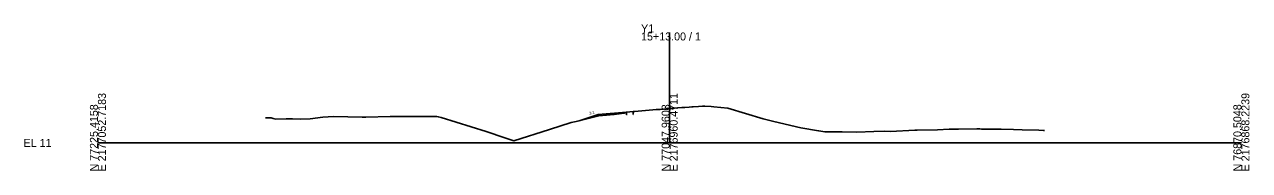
# Model space of a CAD drawing. Extents: x 2207892 to 2209721, y 61220 to 65449.
# Drawn here: x 2209292.5 to 2209721, y 61397.6 to 61448.8 of the extents above; entities that cross this region are included whole.
import ezdxf

# ---------------------------------------------------------------- set-up
doc = ezdxf.new("R2010")
doc.units = 0
for name, color, linetype in [('Exist DTM Breakline Cogo Point CELL', 7, 'Continuous'), ('Exist DTM Ridgeline Cogo Comment', 7, 'Continuous'), ('Exist Hydro Stream or Body of Water Cogo Elevation', 7, 'Continuous'), ('Exist Hydro Stream or Body of Water Cogo Point CELL', 7, 'Continuous'), ('Exist Roads EOP Other Cogo Elevation', 7, 'Continuous'), ('Exist Roads EOP Other Cogo Number', 7, 'Continuous')]:
    doc.layers.add(name, color=color, linetype=linetype)

msp = doc.modelspace()

# ---------------------------------------------------------------- linework, layer by layer
at = {"layer": 'Exist DTM Breakline Cogo Point CELL'}
for p, q in [((2209503.13, 61417.16), (2209503.13, 61418.1)), ((2209505.38, 61417.25), (2209505.38, 61418.31))]:
    msp.add_line(p, q, dxfattribs=at)
at = {"layer": 'Exist Hydro Stream or Body of Water Cogo Elevation'}
msp.add_lwpolyline([(2209493.13, 61417.3), (2209486.49, 61415.09)], dxfattribs=at)
at = {"layer": 'Exist Hydro Stream or Body of Water Cogo Point CELL'}
msp.add_lwpolyline([(2209503.13, 61418.1), (2209493.13, 61417.3)], dxfattribs=at)
at = {"layer": 'Exist Roads EOP Other Cogo Elevation'}
msp.add_lwpolyline([(2209376.82, 61416.13), (2209378.74, 61416.08), (2209379.48, 61415.91), (2209380.41, 61415.62), (2209383.97, 61415.7), (2209386.22, 61415.71), (2209388.9, 61415.61), (2209392.42, 61415.75), (2209396.89, 61416.32), (2209400.57, 61416.57), (2209410.64, 61416.31), (2209411.19, 61416.31), (2209411.92, 61416.32), (2209420.37, 61416.5), (2209434.63, 61416.56), (2209435.69, 61416.54), (2209436.71, 61416.5), (2209437.23, 61416.46), (2209438.23, 61416.18), (2209454.03, 61411.26), (2209460.51, 61409.07), (2209463.66, 61407.98), (2209476.15, 61411.98), (2209483.73, 61414.41), (2209485.46, 61414.83), (2209493.44, 61416.81), (2209498.79, 61417.24), (2209502.26, 61417.73), (2209503.12, 61418.1), (2209505.38, 61418.31), (2209505.97, 61418.34), (2209507.21, 61418.44), (2209508.47, 61418.55), (2209509.76, 61418.66), (2209510.97, 61418.75), (2209512.3, 61418.86), (2209513.47, 61418.95), (2209514.84, 61419.06), (2209515.97, 61419.15), (2209516.98, 61419.23), (2209517.33, 61419.26), (2209517.69, 61419.29), (2209518.47, 61419.36), (2209519.91, 61419.47), (2209520.97, 61419.55), (2209522.45, 61419.66), (2209523.47, 61419.74), (2209524.99, 61419.85), (2209525.97, 61419.92), (2209526.4, 61419.94), (2209528.23, 61420.06), (2209529.71, 61420.16), (2209530.11, 61420.19), (2209530.5, 61420.21), (2209532.64, 61420.04), (2209533.57, 61419.96), (2209538.5, 61419.5), (2209544.7, 61417.6), (2209550.88, 61415.74), (2209554.6, 61414.85), (2209564.02, 61412.6), (2209570.28, 61411.59), (2209572.52, 61411.18), (2209577.5, 61411.16), (2209578.52, 61411.19), (2209583.64, 61411.03), (2209589.6, 61411.26), (2209593.44, 61411.38), (2209595.39, 61411.24), (2209603.91, 61411.74), (2209604.71, 61411.76), (2209611.85, 61411.94), (2209615.97, 61412.11), (2209619.26, 61412.15), (2209625.59, 61412.19), (2209626.68, 61412.18), (2209627.24, 61412.17), (2209634.09, 61412.1), (2209638.51, 61412), (2209641.51, 61411.89), (2209647.27, 61411.72), (2209648.92, 61411.66), (2209649.26, 61411.65)], dxfattribs=at)
at = {"layer": 'Exist Roads EOP Other Cogo Number'}
for p, q in [((2209518.17, 61407.31), (2209518.17, 61446.01)), ((2209318.17, 61407.31), (2209518.17, 61407.31)), ((2209518.17, 61407.31), (2209718.17, 61407.31))]:
    msp.add_line(p, q, dxfattribs=at)

# ---------------------------------------------------------------- texts
at = {"layer": 'Exist DTM Breakline Cogo Point CELL'}
for s, height, p in [('23.02', 1, (2209516.26, 61418.83)), ('EOS', 0.1, (2209503.06, 61416.93)), ('EOP', 0.1, (2209505.29, 61416.93))]:
    msp.add_text(s, height=height, dxfattribs=at).set_placement(p)
at = {"layer": 'Exist DTM Ridgeline Cogo Comment'}
msp.add_text('3:1', height=1, rotation=18.4332, dxfattribs=at).set_placement((2209490.18, 61417.11))
at = {"layer": 'Exist Roads EOP Other Cogo Number'}
for s, p in [('Y1', (2209508.17, 61446.01)), ('15+13.00 / 1', (2209508.17, 61443.21)), ('EL 11', (2209292.17, 61405.91))]:
    msp.add_text(s, height=2.8, dxfattribs=at).set_placement(p)
for s, p in [('E 2177052.7183', (2209320.97, 61397.31)), ('E 2176960.4711', (2209520.97, 61397.31)), ('E 2176868.2239', (2209720.97, 61397.31)), ('N 77225.4158', (2209318.17, 61397.31)), ('N 77047.9603', (2209518.17, 61397.31)), ('N 76870.5048', (2209718.17, 61397.31))]:
    msp.add_text(s, height=2.8, rotation=90, dxfattribs=at).set_placement(p)

doc.saveas('drawing.dxf')
